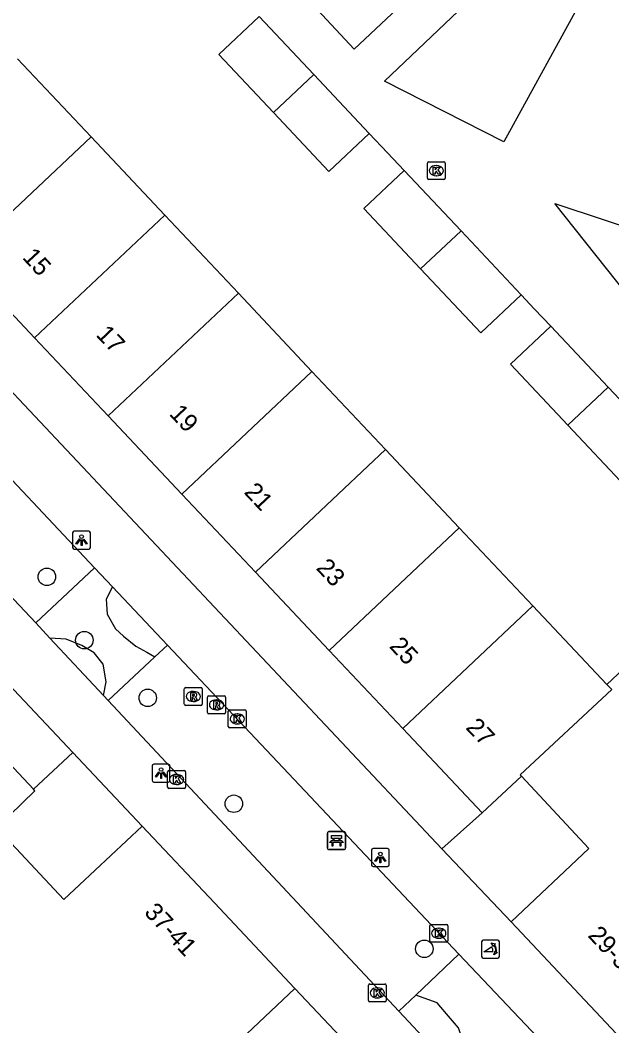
# Model space of a CAD drawing. Extents: x 162542 to 163144, y 380786 to 381511.
# Drawn here: x 162923.8 to 162956.9, y 381201.7 to 381257.9 of the extents above; entities that cross this region are included whole.
import ezdxf

# ---------------------------------------------------------------- set-up
doc = ezdxf.new("R2010")
doc.units = 0
for name, color, linetype in [('IMGEO_Bank', 7, 'Continuous'), ('IMGEO_Boom', 7, 'Continuous'), ('IMGEO_Groenvoorziening', 7, 'Continuous'), ('IMGEO_Hek', 7, 'Continuous'), ('IMGEO_Kolk', 7, 'Continuous'), ('IMGEO_Lichtpunt', 7, 'Continuous'), ('IMGEO_Muur', 7, 'Continuous'), ('IMGEO_Pand', 7, 'Continuous'), ('IMGEO_Pand_nummerreeks', 7, 'Continuous'), ('IMGEO_Poller', 7, 'Continuous'), ('IMGEO_Rioolput', 7, 'Continuous'), ('IMGEO_Voetpad_open', 7, 'Continuous')]:
    doc.layers.add(name, color=color, linetype=linetype)

msp = doc.modelspace()

# ---------------------------------------------------------------- linework, layer by layer
at = {"layer": 'IMGEO_Bank'}
for p, q in [((162940.991, 381211.656), (162940.991, 381212.497)), ((162940.991, 381212.497), (162940.991, 381211.656)), ((162941.066, 381212.581), (162941.907, 381212.581)), ((162941.907, 381212.581), (162941.066, 381212.581)), ((162941.991, 381212.506), (162941.991, 381211.665)), ((162941.991, 381211.665), (162941.991, 381212.506)), ((162941.688, 381211.979), (162941.295, 381211.979)), ((162941.3, 381212.087), (162941.3, 381212.193)), ((162941.344, 381212.193), (162941.344, 381212.087)), ((162941.632, 381212.199), (162941.35, 381212.199)), ((162941.35, 381212.081), (162941.632, 381212.081)), ((162941.638, 381212.087), (162941.638, 381212.193)), ((162941.682, 381212.193), (162941.682, 381212.087)), ((162941.916, 381211.581), (162941.075, 381211.581)), ((162941.075, 381211.581), (162941.916, 381211.581))]:
    msp.add_line(p, q, dxfattribs=at)
for points in [[(162941.294, 381212.199), (162941.208, 381212.199), (162941.208, 381212.36), (162941.771, 381212.36), (162941.771, 381212.199), (162941.688, 381212.199)], [(162941.238, 381211.979), (162941.096, 381211.979), (162941.208, 381212.081), (162941.294, 381212.081)], [(162941.288, 381211.972), (162941.288, 381211.765), (162941.245, 381211.765), (162941.245, 381211.972)], [(162941.688, 381212.081), (162941.771, 381212.081), (162941.883, 381211.979), (162941.744, 381211.979)], [(162941.738, 381211.972), (162941.738, 381211.765), (162941.694, 381211.765), (162941.694, 381211.972)]]:
    msp.add_lwpolyline(points, dxfattribs=at)
for centre, radius, start, end in [((162941.069, 381212.503), 0.0779, 92.4484, 184.2845), ((162941.069, 381212.503), 0.0779, 92.4484, 184.2845), ((162941.913, 381212.503), 0.0779, 2.4484, 94.2845), ((162941.913, 381212.503), 0.0779, 2.4484, 94.2845), ((162941.238, 381211.972), 0.00671, 2.8957, 87.1043), ((162941.295, 381211.972), 0.00671, 92.8957, 177.1043), ((162941.293, 381212.192), 0.00671, 2.8957, 87.1043), ((162941.293, 381212.088), 0.00671, 272.8957, 357.1043), ((162941.35, 381212.192), 0.00671, 92.8957, 177.1043), ((162941.35, 381212.088), 0.00671, 182.8957, 267.1043), ((162941.632, 381212.192), 0.00671, 2.8957, 87.1043), ((162941.632, 381212.088), 0.00671, 272.8957, 357.1043), ((162941.689, 381212.192), 0.00671, 92.8957, 177.1043), ((162941.689, 381212.088), 0.00671, 182.8957, 267.1043), ((162941.687, 381211.972), 0.00671, 2.8957, 87.1043), ((162941.744, 381211.972), 0.00671, 92.8957, 177.1043), ((162941.069, 381211.659), 0.0779, 182.4484, 274.2845), ((162941.069, 381211.659), 0.0779, 182.4484, 274.2845), ((162941.913, 381211.659), 0.0779, 272.4484, 4.2845), ((162941.913, 381211.659), 0.0779, 272.4484, 4.2845)]:
    msp.add_arc(centre, radius, start, end, dxfattribs=at)
at = {"layer": 'IMGEO_Boom'}
for centre in [(162925.316, 381226.816), (162927.406, 381223.279), (162930.95, 381220.054), (162935.761, 381214.137), (162946.396, 381206.032)]:
    msp.add_circle(centre, 0.489, dxfattribs=at)
at = {"layer": 'IMGEO_Groenvoorziening'}
for points in [[(162928.987, 381226.26), (162928.629, 381225.567), (162928.687, 381224.724), (162929.152, 381223.91), (162929.588, 381223.503), (162930.286, 381222.951), (162930.896, 381222.602), (162931.343, 381222.344)], [(162928.487, 381220.193), (162928.629, 381220.945), (162928.454, 381221.933), (162927.96, 381222.573), (162927.262, 381222.98), (162926.39, 381223.329), (162925.489, 381223.396)], [(162948.741, 381198.532), (162948.803, 381199.491), (162948.774, 381200.218), (162948.513, 381200.974), (162948.309, 381201.613), (162947.641, 381202.398), (162947.117, 381203.009), (162945.924, 381203.441)]]:
    msp.add_lwpolyline(points, dxfattribs=at)
at = {"layer": 'IMGEO_Hek'}
for points in [[(162924.559, 381214.952), (162926.773, 381216.999)], [(162926.773, 381216.999), (162930.637, 381212.889)], [(162943.3, 381199.444), (162939.164, 381203.82)]]:
    msp.add_lwpolyline(points, dxfattribs=at)
at = {"layer": 'IMGEO_Kolk'}
for p, q in [((162946.645, 381250.014), (162947.497, 381250.014)), ((162946.57, 381249.088), (162946.57, 381249.94)), ((162947.058, 381249.794), (162947.083, 381249.794)), ((162947.571, 381249.94), (162947.571, 381249.088)), ((162947.497, 381249.014), (162946.645, 381249.014)), ((162947.081, 381249.234), (162947.056, 381249.234)), ((162935.45, 381218.455), (162935.45, 381219.307)), ((162935.525, 381219.381), (162936.377, 381219.381)), ((162935.938, 381219.161), (162935.963, 381219.161)), ((162936.451, 381219.307), (162936.451, 381218.455)), ((162935.961, 381218.601), (162935.936, 381218.601)), ((162936.377, 381218.381), (162935.525, 381218.381)), ((162932.059, 381215.066), (162932.059, 381215.918)), ((162932.134, 381215.992), (162932.986, 381215.992)), ((162932.547, 381215.772), (162932.572, 381215.772)), ((162933.06, 381215.918), (162933.06, 381215.066)), ((162932.57, 381215.212), (162932.545, 381215.212)), ((162932.986, 381214.992), (162932.134, 381214.992)), ((162946.706, 381206.472), (162946.706, 381207.324)), ((162946.781, 381207.398), (162947.633, 381207.398)), ((162947.707, 381207.324), (162947.707, 381206.472)), ((162947.194, 381207.178), (162947.219, 381207.178)), ((162947.633, 381206.398), (162946.781, 381206.398)), ((162947.217, 381206.618), (162947.192, 381206.618)), ((162943.272, 381203.138), (162943.272, 381203.99)), ((162943.347, 381204.064), (162944.199, 381204.064)), ((162944.273, 381203.99), (162944.273, 381203.138)), ((162943.76, 381203.844), (162943.785, 381203.844)), ((162944.199, 381203.064), (162943.347, 381203.064)), ((162943.783, 381203.284), (162943.758, 381203.284))]:
    msp.add_line(p, q, dxfattribs=at)
for points in [[(162946.645, 381250.014), (162947.497, 381250.014)], [(162946.57, 381249.088), (162946.57, 381249.94)], [(162946.891, 381249.714), (162947.014, 381249.714), (162947.014, 381249.563), (162947.144, 381249.714), (162947.308, 381249.714), (162947.162, 381249.563), (162947.315, 381249.314), (162947.163, 381249.314), (162947.078, 381249.478), (162947.014, 381249.411), (162947.014, 381249.314), (162946.891, 381249.314), (162946.891, 381249.714)], [(162947.571, 381249.94), (162947.571, 381249.088)], [(162947.497, 381249.014), (162946.645, 381249.014)], [(162935.45, 381218.455), (162935.45, 381219.307)], [(162935.525, 381219.381), (162936.377, 381219.381)], [(162935.771, 381219.081), (162935.894, 381219.081), (162935.894, 381218.93), (162936.024, 381219.081), (162936.188, 381219.081), (162936.042, 381218.93), (162936.195, 381218.681), (162936.043, 381218.681), (162935.958, 381218.845), (162935.894, 381218.778), (162935.894, 381218.681), (162935.771, 381218.681), (162935.771, 381219.081)], [(162936.451, 381219.307), (162936.451, 381218.455)], [(162936.377, 381218.381), (162935.525, 381218.381)], [(162932.059, 381215.066), (162932.059, 381215.918)], [(162932.134, 381215.992), (162932.986, 381215.992)], [(162933.06, 381215.918), (162933.06, 381215.066)], [(162932.38, 381215.692), (162932.503, 381215.692), (162932.503, 381215.541), (162932.633, 381215.692), (162932.797, 381215.692), (162932.651, 381215.541), (162932.804, 381215.292), (162932.652, 381215.292), (162932.567, 381215.456), (162932.503, 381215.389), (162932.503, 381215.292), (162932.38, 381215.292), (162932.38, 381215.692)], [(162932.986, 381214.992), (162932.134, 381214.992)], [(162946.706, 381206.472), (162946.706, 381207.324)], [(162946.781, 381207.398), (162947.633, 381207.398)], [(162947.707, 381207.324), (162947.707, 381206.472)], [(162947.027, 381207.098), (162947.15, 381207.098), (162947.15, 381206.947), (162947.28, 381207.098), (162947.444, 381207.098), (162947.298, 381206.947), (162947.451, 381206.698), (162947.299, 381206.698), (162947.214, 381206.862), (162947.15, 381206.795), (162947.15, 381206.698), (162947.027, 381206.698), (162947.027, 381207.098)], [(162947.633, 381206.398), (162946.781, 381206.398)], [(162943.272, 381203.138), (162943.272, 381203.99)], [(162943.347, 381204.064), (162944.199, 381204.064)], [(162944.273, 381203.99), (162944.273, 381203.138)], [(162943.593, 381203.764), (162943.716, 381203.764), (162943.716, 381203.613), (162943.846, 381203.764), (162944.01, 381203.764), (162943.864, 381203.613), (162944.017, 381203.364), (162943.865, 381203.364), (162943.78, 381203.528), (162943.716, 381203.461), (162943.716, 381203.364), (162943.593, 381203.364), (162943.593, 381203.764)], [(162944.199, 381203.064), (162943.347, 381203.064)]]:
    msp.add_lwpolyline(points, dxfattribs=at)
for centre, start, end in [((162946.647, 381249.938), 91.552, 178.448), ((162946.647, 381249.938), 91.552, 178.448), ((162947.495, 381249.938), 1.552, 88.448), ((162947.495, 381249.938), 1.552, 88.448), ((162946.647, 381249.09), 181.552, 268.448), ((162946.647, 381249.09), 181.552, 268.448), ((162947.495, 381249.09), 271.552, 358.448), ((162947.495, 381249.09), 271.552, 358.448), ((162935.527, 381219.305), 91.552, 178.448), ((162935.527, 381219.305), 91.552, 178.448), ((162936.375, 381219.305), 1.552, 88.448), ((162936.375, 381219.305), 1.552, 88.448), ((162935.527, 381218.457), 181.552, 268.448), ((162935.527, 381218.457), 181.552, 268.448), ((162936.375, 381218.457), 271.552, 358.448), ((162936.375, 381218.457), 271.552, 358.448), ((162932.136, 381215.916), 91.552, 178.448), ((162932.136, 381215.916), 91.552, 178.448), ((162932.984, 381215.916), 1.552, 88.448), ((162932.984, 381215.916), 1.552, 88.448), ((162932.136, 381215.068), 181.552, 268.448), ((162932.136, 381215.068), 181.552, 268.448), ((162932.984, 381215.068), 271.552, 358.448), ((162932.984, 381215.068), 271.552, 358.448), ((162946.783, 381207.322), 91.552, 178.448), ((162946.783, 381207.322), 91.552, 178.448), ((162947.631, 381207.322), 1.552, 88.448), ((162947.631, 381207.322), 1.552, 88.448), ((162946.783, 381206.474), 181.552, 268.448), ((162946.783, 381206.474), 181.552, 268.448), ((162947.631, 381206.474), 271.552, 358.448), ((162947.631, 381206.474), 271.552, 358.448), ((162943.349, 381203.988), 91.552, 178.448), ((162943.349, 381203.988), 91.552, 178.448), ((162944.197, 381203.988), 1.552, 88.448), ((162944.197, 381203.988), 1.552, 88.448), ((162943.349, 381203.14), 181.552, 268.448), ((162943.349, 381203.14), 181.552, 268.448), ((162944.197, 381203.14), 271.552, 358.448), ((162944.197, 381203.14), 271.552, 358.448)]:
    msp.add_arc(centre, 0.0765, start, end, dxfattribs=at)
for centre, major_axis, ratio, start_param, end_param in [((162947.057, 381249.514), (-0.387, 0.002), 0.722429, 4.712389, 7.853982), ((162947.082, 381249.514), (-0.39, 0.002), 0.717154, 1.570796, 4.712389), ((162935.937, 381218.881), (-0.387, 0.002), 0.722429, 4.712389, 7.853982), ((162935.962, 381218.881), (-0.39, 0.002), 0.717154, 1.570796, 4.712389), ((162932.546, 381215.492), (-0.387, 0.002), 0.722429, 4.712389, 7.853982), ((162932.571, 381215.492), (-0.39, 0.002), 0.717154, 1.570796, 4.712389), ((162947.193, 381206.898), (-0.387, 0.002), 0.722429, 4.712389, 7.853982), ((162947.218, 381206.898), (-0.39, 0.002), 0.717154, 1.570796, 4.712389), ((162943.759, 381203.564), (-0.387, 0.002), 0.722429, 4.712389, 7.853982), ((162943.784, 381203.564), (-0.39, 0.002), 0.717154, 1.570796, 4.712389)]:
    msp.add_ellipse(centre, major_axis=major_axis, ratio=ratio, start_param=start_param, end_param=end_param, dxfattribs=at)
at = {"layer": 'IMGEO_Lichtpunt'}
for p, q in [((162926.754, 381229.268), (162926.754, 381228.461)), ((162926.754, 381229.268), (162926.754, 381228.461)), ((162927.656, 381229.363), (162926.848, 381229.363)), ((162927.656, 381229.363), (162926.848, 381229.363)), ((162927.75, 381228.461), (162927.75, 381229.268)), ((162927.75, 381228.461), (162927.75, 381229.268)), ((162926.848, 381228.367), (162927.656, 381228.367)), ((162926.848, 381228.367), (162927.656, 381228.367)), ((162932.098, 381216.348), (162931.29, 381216.348)), ((162932.098, 381216.348), (162931.29, 381216.348)), ((162931.196, 381216.253), (162931.196, 381215.446)), ((162931.196, 381216.253), (162931.196, 381215.446)), ((162932.192, 381215.446), (162932.192, 381216.253)), ((162932.192, 381215.446), (162932.192, 381216.253)), ((162931.29, 381215.352), (162932.098, 381215.352)), ((162931.29, 381215.352), (162932.098, 381215.352)), ((162943.447, 381211.534), (162943.447, 381210.727)), ((162943.447, 381211.534), (162943.447, 381210.727)), ((162944.349, 381211.629), (162943.541, 381211.629)), ((162944.349, 381211.629), (162943.541, 381211.629)), ((162944.443, 381210.727), (162944.443, 381211.534)), ((162944.443, 381210.727), (162944.443, 381211.534)), ((162943.541, 381210.633), (162944.349, 381210.633)), ((162943.541, 381210.633), (162944.349, 381210.633))]:
    msp.add_line(p, q, dxfattribs=at)
for points in [[(162927.128, 381228.932), (162927.167, 381228.904), (162926.979, 381228.642), (162926.941, 381228.669), (162927.128, 381228.932)], [(162927.23, 381228.884), (162927.277, 381228.884), (162927.277, 381228.562), (162927.23, 381228.562), (162927.23, 381228.884)], [(162927.34, 381228.904), (162927.378, 381228.931), (162927.565, 381228.669), (162927.526, 381228.641), (162927.34, 381228.904)], [(162931.57, 381215.917), (162931.609, 381215.889), (162931.421, 381215.627), (162931.383, 381215.654), (162931.57, 381215.917)], [(162931.672, 381215.869), (162931.719, 381215.869), (162931.719, 381215.547), (162931.672, 381215.547), (162931.672, 381215.869)], [(162931.782, 381215.889), (162931.82, 381215.916), (162932.007, 381215.654), (162931.968, 381215.626), (162931.782, 381215.889)], [(162943.821, 381211.198), (162943.86, 381211.17), (162943.672, 381210.908), (162943.634, 381210.935), (162943.821, 381211.198)], [(162943.923, 381211.15), (162943.97, 381211.15), (162943.97, 381210.828), (162943.923, 381210.828), (162943.923, 381211.15)], [(162944.033, 381211.17), (162944.071, 381211.197), (162944.258, 381210.935), (162944.219, 381210.907), (162944.033, 381211.17)]]:
    msp.add_lwpolyline(points, dxfattribs=at)
for centre in [(162927.253, 381229.066), (162931.695, 381216.051), (162943.946, 381211.332)]:
    msp.add_circle(centre, 0.0994, dxfattribs=at)
for centre, start, end in [((162926.848, 381229.268), 90, 180), ((162926.848, 381229.268), 90, 180), ((162927.656, 381229.268), 0, 90), ((162927.656, 381229.268), 0, 90), ((162926.848, 381228.461), 180, 270), ((162926.848, 381228.461), 180, 270), ((162927.656, 381228.461), 270, 0), ((162927.656, 381228.461), 270, 360), ((162931.29, 381216.253), 90, 180), ((162931.29, 381216.253), 90, 180), ((162932.098, 381216.253), 0, 90), ((162932.098, 381216.253), 0, 90), ((162931.29, 381215.446), 180, 270), ((162931.29, 381215.446), 180, 270), ((162932.098, 381215.446), 270, 0), ((162932.098, 381215.446), 270, 360), ((162943.541, 381211.534), 90, 180), ((162943.541, 381211.534), 90, 180), ((162944.349, 381211.534), 0, 90), ((162944.349, 381211.534), 0, 90), ((162943.541, 381210.727), 180, 270), ((162943.541, 381210.727), 180, 270), ((162944.349, 381210.727), 270, 0), ((162944.349, 381210.727), 270, 360)]:
    msp.add_arc(centre, 0.0946, start, end, dxfattribs=at)
at = {"layer": 'IMGEO_Muur'}
for points in [[(162947.383, 381211.626), (162949.627, 381213.623)], [(162951.248, 381207.533), (162947.383, 381211.626)]]:
    msp.add_lwpolyline(points, dxfattribs=at)
at = {"layer": 'IMGEO_Pand'}
for points in [[(162946.098, 381259.71), (162942.489, 381256.312), (162940.432, 381258.495)], [(162937.17, 381258.126), (162934.914, 381255.999), (162937.967, 381252.758)], [(162937.17, 381258.126), (162940.222, 381254.884)], [(162927.784, 381251.402), (162923.671, 381255.771)], [(162937.967, 381252.758), (162940.222, 381254.884)], [(162940.222, 381254.884), (162943.314, 381251.6)], [(162937.967, 381252.758), (162941.059, 381249.474), (162943.314, 381251.6)], [(162927.784, 381251.402), (162920.51, 381244.542)], [(162931.897, 381247.034), (162927.784, 381251.402)], [(162946.193, 381244.021), (162943.017, 381247.394), (162945.272, 381249.521)], [(162945.272, 381249.521), (162948.448, 381246.148)], [(162931.897, 381247.034), (162924.623, 381240.174)], [(162936.01, 381242.665), (162931.897, 381247.034)], [(162948.448, 381246.148), (162946.193, 381244.021)], [(162948.448, 381246.148), (162951.811, 381242.578)], [(162920.51, 381244.542), (162924.623, 381240.174)], [(162951.811, 381242.578), (162949.554, 381240.452), (162946.193, 381244.021)], [(162928.737, 381235.806), (162936.01, 381242.665)], [(162940.123, 381238.297), (162936.01, 381242.665)], [(162953.464, 381240.822), (162951.208, 381238.695), (162954.42, 381235.285)], [(162953.464, 381240.822), (162956.675, 381237.412)], [(162924.623, 381240.174), (162928.737, 381235.806)], [(162932.85, 381231.438), (162940.123, 381238.297)], [(162944.236, 381233.928), (162940.123, 381238.297)], [(162956.675, 381237.412), (162954.42, 381235.285)], [(162956.675, 381237.412), (162959.887, 381234)], [(162928.737, 381235.806), (162932.85, 381231.438)], [(162954.42, 381235.285), (162957.632, 381231.874), (162959.887, 381234)], [(162936.964, 381227.07), (162944.236, 381233.928)], [(162948.349, 381229.56), (162944.236, 381233.928)], [(162936.964, 381227.07), (162932.85, 381231.438)], [(162948.349, 381229.56), (162941.077, 381222.702)], [(162952.462, 381225.191), (162948.349, 381229.56)], [(162941.077, 381222.702), (162936.964, 381227.07)], [(162962.674, 381226.519), (162956.596, 381220.8)], [(162952.462, 381225.191), (162945.19, 381218.334)], [(162956.596, 381220.8), (162952.462, 381225.191)], [(162941.077, 381222.702), (162945.19, 381218.334)], [(162956.596, 381220.8), (162956.867, 381220.513), (162951.756, 381215.746), (162951.824, 381215.673)], [(162922.498, 381212.786), (162924.643, 381214.864), (162924.559, 381214.952), (162920.372, 381219.397)], [(162945.19, 381218.334), (162949.627, 381213.623), (162951.824, 381215.673)], [(162951.824, 381215.673), (162955.597, 381211.645), (162951.248, 381207.533)], [(162930.637, 381212.889), (162926.266, 381208.779), (162922.498, 381212.786)], [(162930.637, 381212.889), (162934.676, 381208.594), (162939.164, 381203.82)], [(162959.774, 381198.46), (162951.248, 381207.533)], [(162938.919, 381195.337), (162934.812, 381199.7), (162939.164, 381203.82)]]:
    msp.add_lwpolyline(points, dxfattribs=at)
at = {"layer": 'IMGEO_Poller'}
for p, q in [((162949.596, 381206.414), (162949.596, 381205.607)), ((162949.596, 381206.414), (162949.596, 381205.607)), ((162950.498, 381206.509), (162949.69, 381206.509)), ((162950.498, 381206.509), (162949.69, 381206.509)), ((162950.592, 381205.607), (162950.592, 381206.414)), ((162950.592, 381205.607), (162950.592, 381206.414)), ((162949.69, 381205.512), (162950.498, 381205.512)), ((162949.69, 381205.512), (162950.498, 381205.512))]:
    msp.add_line(p, q, dxfattribs=at)
for points in [[(162950.275, 381206.238), (162950.263, 381206.165), (162950.138, 381206.37)], [(162950.138, 381206.37), (162950.369, 381206.304), (162950.298, 381206.272)], [(162950.231, 381205.865), (162949.718, 381205.865), (162950.148, 381206.14)], [(162950.291, 381205.693), (162950.357, 381205.924), (162950.387, 381205.856)], [(162950.423, 381205.829), (162950.495, 381205.818), (162950.291, 381205.693)]]:
    msp.add_lwpolyline(points, dxfattribs=at)
for centre, radius, start, end in [((162949.69, 381206.414), 0.0946, 90, 180), ((162949.69, 381206.414), 0.0946, 90, 180), ((162949.917, 381205.925), 0.476, 351.7527, 41.1691), ((162949.917, 381205.925), 0.516, 349.3569, 42.2912), ((162950.498, 381206.414), 0.0946, 0, 90), ((162950.498, 381206.414), 0.0946, 0, 90), ((162949.69, 381205.607), 0.0946, 180, 270), ((162949.69, 381205.607), 0.0946, 180, 270), ((162949.903, 381205.915), 0.332, 351.3247, 42.4854), ((162950.498, 381205.607), 0.0946, 270, 0), ((162950.498, 381205.607), 0.0946, 270, 0)]:
    msp.add_arc(centre, radius, start, end, dxfattribs=at)
at = {"layer": 'IMGEO_Rioolput'}
for p, q in [((162932.993, 381219.704), (162932.993, 381220.556)), ((162933.068, 381220.63), (162933.92, 381220.63)), ((162933.481, 381220.41), (162933.506, 381220.41)), ((162933.994, 381220.556), (162933.994, 381219.704)), ((162933.504, 381219.85), (162933.479, 381219.85)), ((162934.29, 381219.238), (162934.29, 381220.09)), ((162934.365, 381220.164), (162935.217, 381220.164)), ((162934.778, 381219.944), (162934.803, 381219.944)), ((162935.291, 381220.09), (162935.291, 381219.238)), ((162933.92, 381219.63), (162933.068, 381219.63)), ((162935.217, 381219.164), (162934.365, 381219.164)), ((162934.801, 381219.384), (162934.776, 381219.384))]:
    msp.add_line(p, q, dxfattribs=at)
for points in [[(162932.993, 381219.704), (162932.993, 381220.556)], [(162933.068, 381220.63), (162933.92, 381220.63)], [(162933.582, 381220.328), (162933.33, 381220.33), (162933.33, 381219.93)], [(162933.508, 381220.249), (162933.454, 381220.249), (162933.454, 381220.168)], [(162933.994, 381220.556), (162933.994, 381219.704)], [(162933.33, 381219.93), (162933.454, 381219.93), (162933.454, 381220.092), (162933.465, 381220.092)], [(162933.454, 381220.168), (162933.506, 381220.168)], [(162933.512, 381220.063), (162933.583, 381219.93), (162933.723, 381219.93), (162933.658, 381220.056)], [(162934.29, 381219.238), (162934.29, 381220.09)], [(162934.365, 381220.164), (162935.217, 381220.164)], [(162934.879, 381219.862), (162934.627, 381219.864), (162934.627, 381219.464)], [(162934.805, 381219.783), (162934.751, 381219.783), (162934.751, 381219.702)], [(162934.751, 381219.702), (162934.803, 381219.702)], [(162935.291, 381220.09), (162935.291, 381219.238)], [(162933.92, 381219.63), (162933.068, 381219.63)], [(162935.217, 381219.164), (162934.365, 381219.164)], [(162934.627, 381219.464), (162934.751, 381219.464), (162934.751, 381219.626), (162934.762, 381219.626)], [(162934.809, 381219.597), (162934.88, 381219.464), (162935.02, 381219.464), (162934.955, 381219.59)]]:
    msp.add_lwpolyline(points, dxfattribs=at)
for centre, radius, start, end in [((162933.07, 381220.554), 0.0765, 91.552, 178.448), ((162933.07, 381220.554), 0.0765, 91.552, 178.448), ((162933.514, 381220.153), 0.0964, 77.0061, 93.1865), ((162933.528, 381220.21), 0.0378, 276.6634, 79.6772), ((162933.581, 381220.218), 0.109, 350.3612, 89.416), ((162933.918, 381220.554), 0.0765, 1.552, 88.448), ((162933.918, 381220.554), 0.0765, 1.552, 88.448), ((162933.07, 381219.706), 0.0765, 181.552, 268.448), ((162933.07, 381219.706), 0.0765, 181.552, 268.448), ((162933.464, 381220.039), 0.0533, 26.0293, 88.6989), ((162933.49, 381220.357), 0.19, 274.7715, 282.9687), ((162933.579, 381220.218), 0.112, 277.5842, 350.9817), ((162933.563, 381220.003), 0.108, 29.5134, 73.7905), ((162933.918, 381219.706), 0.0765, 271.552, 358.448), ((162933.918, 381219.706), 0.0765, 271.552, 358.448), ((162934.367, 381220.088), 0.0765, 91.552, 178.448), ((162934.367, 381220.088), 0.0765, 91.552, 178.448), ((162934.787, 381219.891), 0.19, 274.7715, 282.9687), ((162934.811, 381219.687), 0.0964, 77.0061, 93.1865), ((162934.825, 381219.744), 0.0378, 276.6634, 79.6772), ((162934.878, 381219.752), 0.109, 350.3612, 89.416), ((162934.876, 381219.752), 0.112, 277.5842, 350.9817), ((162934.86, 381219.537), 0.108, 29.5134, 73.7905), ((162935.215, 381220.088), 0.0765, 1.552, 88.448), ((162935.215, 381220.088), 0.0765, 1.552, 88.448), ((162934.367, 381219.24), 0.0765, 181.552, 268.448), ((162934.367, 381219.24), 0.0765, 181.552, 268.448), ((162934.761, 381219.573), 0.0533, 26.0293, 88.6989), ((162935.215, 381219.24), 0.0765, 271.552, 358.448), ((162935.215, 381219.24), 0.0765, 271.552, 358.448)]:
    msp.add_arc(centre, radius, start, end, dxfattribs=at)
for centre, major_axis, ratio, start_param, end_param in [((162933.48, 381220.13), (-0.387, 0.002), 0.722429, 4.712389, 7.853982), ((162933.505, 381220.13), (-0.39, 0.002), 0.717154, 1.570796, 4.712389), ((162934.777, 381219.664), (-0.387, 0.002), 0.722429, 4.712389, 7.853982), ((162934.802, 381219.664), (-0.39, 0.002), 0.717154, 1.570796, 4.712389)]:
    msp.add_ellipse(centre, major_axis=major_axis, ratio=ratio, start_param=start_param, end_param=end_param, dxfattribs=at)
at = {"layer": 'IMGEO_Voetpad_open'}
for points in [[(162950.849, 381251.129), (162944.181, 381254.516), (162961.75, 381271.244), (162970.642, 381259.25), (162967.083, 381253.164), (162955.438, 381259.527), (162950.849, 381251.129)], [(162971.877, 381257.641), (162974.693, 381253.841), (162982.743, 381249.335), (162965.303, 381233.048), (162953.697, 381247.671), (162964.763, 381244.019), (162971.877, 381257.641)], [(162951.248, 381207.533), (162947.383, 381211.626), (162906.029, 381255.574)], [(162943.314, 381251.6), (162944.335, 381250.516), (162945.272, 381249.521)], [(162897.699, 381247.866), (162926.773, 381216.999), (162930.637, 381212.889)], [(162951.811, 381242.578), (162952.562, 381241.78), (162953.464, 381240.822)], [(162914.411, 381241.729), (162918.482, 381237.409), (162927.981, 381227.327)], [(162924.695, 381224.244), (162915.191, 381234.33), (162911.139, 381238.659)], [(162927.981, 381227.327), (162924.695, 381224.244)], [(162927.981, 381227.327), (162928.987, 381226.26)], [(162928.987, 381226.26), (162932.052, 381223.007)], [(162925.489, 381223.396), (162924.695, 381224.244)], [(162928.487, 381220.193), (162925.489, 381223.396)], [(162931.343, 381222.344), (162932.052, 381223.007)], [(162932.052, 381223.007), (162948.336, 381205.724)], [(162931.343, 381222.344), (162928.747, 381219.915)], [(162928.747, 381219.915), (162928.487, 381220.193)], [(162944.983, 381202.551), (162928.747, 381219.915)], [(162945.924, 381203.441), (162948.336, 381205.724)], [(162948.336, 381205.724), (162952.72, 381201.096), (162949.331, 381197.901), (162948.741, 381198.532)], [(162939.164, 381203.82), (162943.3, 381199.444), (162938.919, 381195.337)], [(162945.924, 381203.441), (162944.983, 381202.551)], [(162948.741, 381198.532), (162944.983, 381202.551)]]:
    msp.add_lwpolyline(points, dxfattribs=at)

# ---------------------------------------------------------------- texts
at = {"layer": 'IMGEO_Pand_nummerreeks'}
for s, rotation, p in [('15', 312.7974, (162923.9, 381244.638)), ('17', 313.7106, (162928.015, 381240.305)), ('19', 313.3424, (162932.111, 381235.89)), ('21', 313.1642, (162936.284, 381231.515)), ('23', 313.1693, (162940.311, 381227.276)), ('25', 312.9546, (162944.402, 381222.902)), ('27', 313.5679, (162948.669, 381218.357)), ('37-41', 313.2409, (162930.705, 381208.027)), ('29-35', 313.2568, (162955.491, 381206.74))]:
    msp.add_text(s, height=1, rotation=rotation, dxfattribs=at).set_placement(p)

doc.saveas('drawing.dxf')
